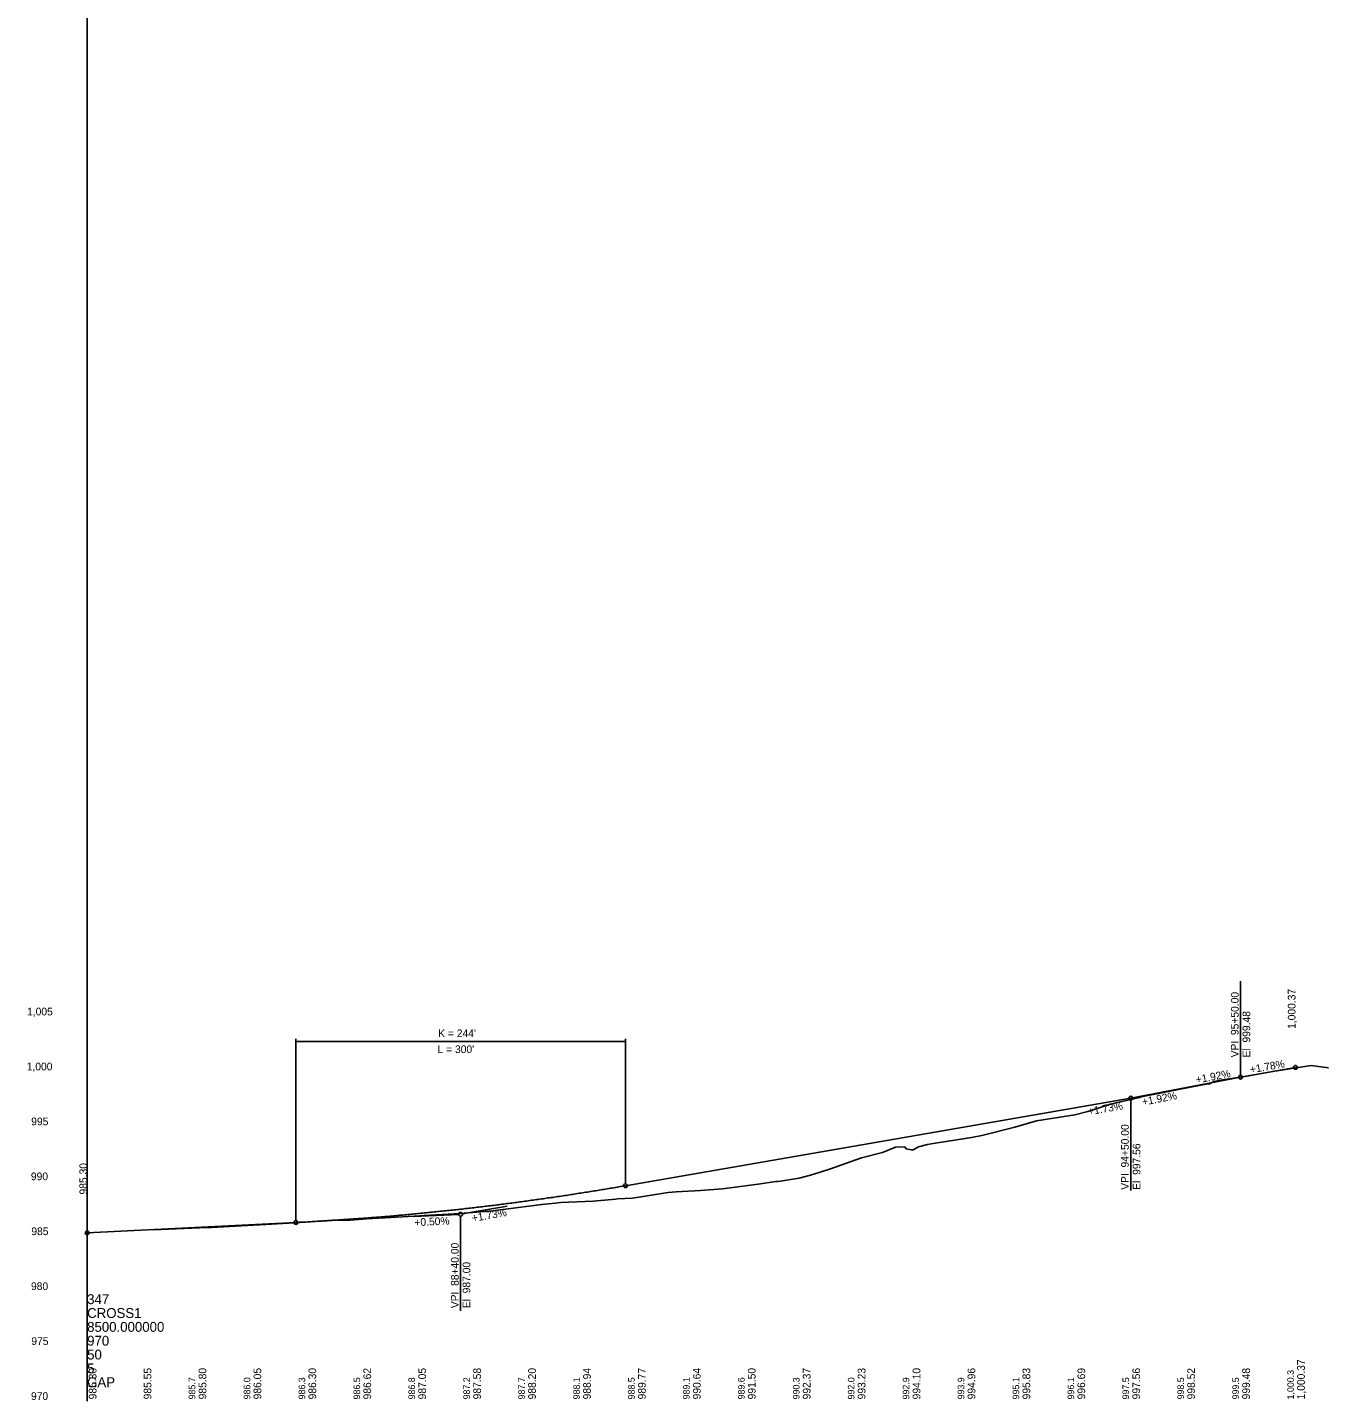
# Model space of a CAD drawing. Extents: x 359946 to 361600, y 170500 to 175500.
# Drawn here: x 359946 to 361130, y 173000 to 174250 of the extents above; entities that cross this region are included whole.
import ezdxf

# ---------------------------------------------------------------- set-up
doc = ezdxf.new("R2010")
doc.units = 0
for name, color, linetype in [('Default', 7, 'Continuous'), ('E_PROF_Grades', 7, 'Continuous'), ('P_E_PROF', 7, 'Continuous'), ('P_PROF', 7, 'Continuous'), ('P_PROF_Grades', 7, 'Continuous')]:
    doc.layers.add(name, color=color, linetype=linetype)

msp = doc.modelspace()

# ---------------------------------------------------------------- linework, layer by layer
at = {"layer": 'Default'}
msp.add_line((360000, 173000), (360000, 175500), dxfattribs=at)
at = {"layer": 'P_E_PROF'}
msp.add_lwpolyline([(360060.5, 173155.9), (360066.4, 173156), (360067.2, 173156), (360102.3, 173157.5), (360113.2, 173157.9), (360146, 173159.7), (360162.7, 173160.6), (360193.9, 173162.4), (360205.3, 173163.3), (360223.5, 173164.7), (360230.6, 173164.7), (360235.7, 173164.4), (360254.4, 173165.8), (360276.6, 173167.1), (360303, 173168.5), (360304.7, 173168.7), (360306.5, 173168.8), (360339.7, 173170.6), (360354.5, 173172), (360369.4, 173173.2), (360380.7, 173174.6), (360413.8, 173178.9), (360426.1, 173180.1), (360431.1, 173180.6), (360460.7, 173182), (360481.4, 173183.8), (360482.9, 173183.9), (360496.5, 173184.7), (360528.8, 173189.8), (360536.2, 173190.3), (360558.4, 173191.6), (360578.4, 173193), (360610.7, 173197.4), (360626.9, 173199.7), (360628.5, 173199.9), (360631.3, 173200.2), (360633, 173200.5), (360648.2, 173203), (360658.6, 173205.7), (360668.3, 173208.6), (360676.7, 173211.2), (360704.9, 173221.3), (360724.1, 173226.2), (360736, 173231), (360736, 173231), (360744.3, 173231.5), (360745.5, 173229.7), (360750.5, 173228.6), (360750.8, 173228.5), (360751.4, 173228.5), (360752, 173228.7), (360756.7, 173231.3), (360765.1, 173233.5), (360768.2, 173234), (360805, 173239.8), (360814.5, 173241.8), (360844.5, 173249.2), (360864.3, 173255), (360899.2, 173260.4), (360910.9, 173263.6), (360931.7, 173270.3), (360957.9, 173276.4), (360959.4, 173276.8), (360990.5, 173282.9), (361006, 173286.1), (361018.7, 173288.3), (361021.9, 173288.8), (361023.2, 173289.5), (361026, 173290.8), (361033.6, 173292.3), (361055.8, 173295.7), (361079.3, 173300), (361114.2, 173305.4), (361114.2, 173305.4), (361114.3, 173305.4), (361130.1, 173303.3)], dxfattribs=at)
at = {"layer": 'P_PROF'}
for p, q in [((360950, 173275.6), (361050, 173294.8)), ((361050, 173294.8), (361100, 173303.7)), ((360490, 173196), (360950, 173275.6)), ((360000, 173153), (360190, 173162.5))]:
    msp.add_line(p, q, dxfattribs=at)
msp.add_spline([(360190, 173162.5), (360196, 173162.8), (360202, 173163.1), (360208, 173163.5), (360214, 173163.8), (360220, 173164.2), (360226, 173164.6), (360232, 173165), (360238, 173165.4), (360244, 173165.8), (360250, 173166.2), (360256, 173166.7), (360262, 173167.2), (360268, 173167.6), (360274, 173168.1), (360280, 173168.7), (360286, 173169.2), (360292, 173169.7), (360298, 173170.3), (360304, 173170.9), (360310, 173171.5), (360316, 173172.1), (360322, 173172.7), (360328, 173173.3), (360334, 173174), (360340, 173174.6), (360346, 173175.3), (360352, 173176), (360358, 173176.7), (360364, 173177.4), (360370, 173178.1), (360376, 173178.9), (360382, 173179.7), (360388, 173180.4), (360394, 173181.2), (360400, 173182), (360406, 173182.9), (360412, 173183.7), (360418, 173184.6), (360424, 173185.4), (360430, 173186.3), (360436, 173187.2), (360442, 173188.1), (360448, 173189.1), (360454, 173190), (360460, 173191), (360466, 173191.9), (360472, 173192.9), (360478, 173193.9), (360484, 173194.9), (360490, 173196)], degree=3, dxfattribs=at)
at = {"layer": 'P_PROF_Grades'}
for p, q in [((361050, 173296.6), (361050, 173382.1)), ((360190, 173329.7), (360190, 173164.2)), ((360190, 173327.2), (360490, 173327.2)), ((360490, 173329.7), (360490, 173197.7)), ((360950, 173273.9), (360950, 173191.6)), ((360297.1, 173167.9), (360338.3, 173169.9)), ((360382.4, 173177.3), (360341.7, 173170.3)), ((360340, 173168.2), (360340, 173082.2))]:
    msp.add_line(p, q, dxfattribs=at)
for centre in [(361050, 173294.8), (361100, 173303.7), (360950, 173275.6), (360490, 173196), (360340, 173170), (360190, 173162.5), (360000, 173153)]:
    msp.add_circle(centre, 1.75, dxfattribs=at)

# ---------------------------------------------------------------- texts
at = {"layer": 'Default'}
for s, p in [('347', (360000, 173088.2)), ('CROSS1', (360000, 173075.6)), ('8500.000000', (360000, 173063)), ('970', (360000, 173050.4)), ('50', (360000, 173037.8)), ('5', (360000, 173025.2)), ('GAP', (360000, 173012.6))]:
    msp.add_text(s, height=9, dxfattribs=at).set_placement(p)
at = {"layer": 'E_PROF_Grades'}
for s, p in [('1,005', (359945.3, 173351)), ('1,000', (359945, 173301)), ('995', (359949.1, 173251)), ('990', (359948.8, 173201)), ('985', (359949.2, 173151)), ('980', (359948.9, 173101)), ('975', (359949.2, 173051)), ('970', (359948.9, 173001))]:
    msp.add_text(s, height=7, dxfattribs=at).set_placement(p)
for s, p in [('985.7', (360098.5, 173001.5)), ('986.0', (360148.5, 173001.5)), ('986.3', (360198.5, 173001.5)), ('986.5', (360248.5, 173001.5)), ('986.8', (360298.5, 173001.5)), ('987.2', (360348.5, 173001.5)), ('987.7', (360398.5, 173001.5)), ('988.1', (360448.5, 173001.5)), ('988.5', (360498.5, 173001.5)), ('989.1', (360548.5, 173001.5)), ('989.6', (360598.5, 173001.5)), ('990.3', (360648.5, 173001.5)), ('992.0', (360698.5, 173001.5)), ('992.9', (360748.5, 173001.5)), ('993.9', (360798.5, 173001.5)), ('995.1', (360848.5, 173001.5)), ('996.1', (360898.5, 173001.5)), ('997.5', (360948.5, 173001.5)), ('998.5', (360998.5, 173001.5)), ('999.5', (361048.5, 173001.5)), ('1,000.3', (361098.5, 173001.5))]:
    msp.add_text(s, height=6, rotation=90, dxfattribs=at).set_placement(p)
at = {"layer": 'P_PROF_Grades'}
for s, rotation, p in [('VPI  95+50.00', 90, (361048.2, 173312.8)), ('1,000.37', 90, (361100, 173338.7)), ('El  999.48', 90, (361058.8, 173312.8)), ('+1.78%', 10.0707, (361059.1, 173298.2)), ('+1.92%', 10.8796, (361009.9, 173288.9)), ('+1.92%', 10.8796, (360961, 173268.8)), ('+1.73%', 9.8214, (360911.7, 173260.1)), ('VPI  94+50.00', 90, (360948.2, 173192.3)), ('El  997.56', 90, (360958.8, 173192.3)), ('985.30', 90, (360000, 173188)), ('+1.73%', 9.8214, (360350.9, 173163)), ('+0.50%', 2.8624, (360298.1, 173159.1)), ('VPI  88+40.00', 90, (360338.2, 173084.5)), ('El  987.00', 90, (360348.8, 173084.5)), ('1,000.37', 90, (361108.5, 173001.5)), ('985.30', 90, (360008.5, 173001.5)), ('985.55', 90, (360058.5, 173001.5)), ('985.80', 90, (360108.5, 173001.5)), ('986.05', 90, (360158.5, 173001.5)), ('986.30', 90, (360208.5, 173001.5)), ('986.62', 90, (360258.5, 173001.5)), ('987.05', 90, (360308.5, 173001.5)), ('987.58', 90, (360358.5, 173001.5)), ('988.20', 90, (360408.5, 173001.5)), ('988.94', 90, (360458.5, 173001.5)), ('989.77', 90, (360508.5, 173001.5)), ('990.64', 90, (360558.5, 173001.5)), ('991.50', 90, (360608.5, 173001.5)), ('992.37', 90, (360658.5, 173001.5)), ('993.23', 90, (360708.5, 173001.5)), ('994.10', 90, (360758.5, 173001.5)), ('994.96', 90, (360808.5, 173001.5)), ('995.83', 90, (360858.5, 173001.5)), ('996.69', 90, (360908.5, 173001.5)), ('997.56', 90, (360958.5, 173001.5)), ('998.52', 90, (361008.5, 173001.5)), ('999.48', 90, (361058.5, 173001.5))]:
    msp.add_text(s, height=7, rotation=rotation, dxfattribs=at).set_placement(p)
for s, p in [("K = 244'", (360319.6, 173331.2)), ("L = 300'", (360319, 173316.7))]:
    msp.add_text(s, height=7, dxfattribs=at).set_placement(p)

doc.saveas('drawing.dxf')
